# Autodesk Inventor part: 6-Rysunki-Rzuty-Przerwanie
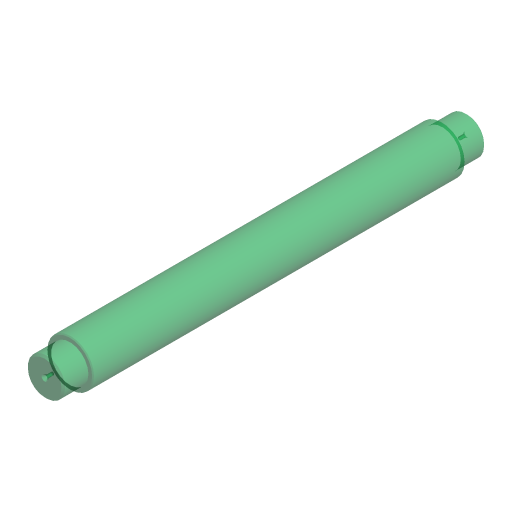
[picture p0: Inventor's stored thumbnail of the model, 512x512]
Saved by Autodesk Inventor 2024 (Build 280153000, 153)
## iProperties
Company: ATC
Shininess: 20.0
Length Units: 11269
Angle Units: 11279
Time Units: 11290
Mass Units: 11283
Length Display Precision: 3
Angle Display Precision: 2
Created: 2023-03
Part Number: 6-Rysunki-Rzuty-Przerwanie
Document SubType Name: Modeling
Designer: Andrzej Jaskulski
Density: 1 g/cm^3
Material: Default
Appearance: Green(Clear)
Checked By: A.J.
Engr Approved By: Andrzej Jaskulski
Mfg Approved By: Andrzej Jaskulski
Authority: A.J.
Density: 0.0
Volumn: 0.0
Area: 0.0
PropertySet Name: Model Information
Control State: 0
Master: False
Checked Out: False
Title: A.J.: Kurs R2024-MEP
Author: Andrzej Jaskulski
Revision Number: 1/24
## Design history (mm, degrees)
node "Czop środkowy" dims "d1" = 200 (= dlugosc), "d2" = 0
  sketch "Sketch1"
    geometry: C1 r 12.5 at (0, 0)
    constraints: 1 centre point
    dimensions: "d3" = 25 diameter of C1
chamfer "Faza1" distance "d33" = 0.5; stored, may be unused: second distance "d34" = 0.5, angle "d35" = 45 deg
workaxis "Work Axis1"
node "Płaszczyzna lustra"
node "Czop końcowy" dims "d5" = 13.5, "d6" = 0
  sketch "Sketch2"
    geometry: C1 r 12.5 at (0, 0) reference; C2 r 10 at (0, 0)
    constraints: 1 centre point, 1 coincident
    dimensions: "d4" = 20 diameter of C2
node "Nakiełek" dims "d9" = 1.6, "d10" = 3.35, "d11" = 2, "d12" = 60 deg, "d13" = 4.3, "d14" = 120 deg, "d30" = 6
  sketch "Sketch3"
    geometry: C1 r 10 at (0, 0) reference; 1 further point
    constraints: 1 coincident
node "Faza2" dims "d15" = 1, "d16" = 1, "d36" = 45 deg
mirror "Lustro2"
node "Bryła1"
node "Korpusy bryłowe"
node "Korpusy powierzchniowe"
other parameters: "d24" = 45 (derived)
